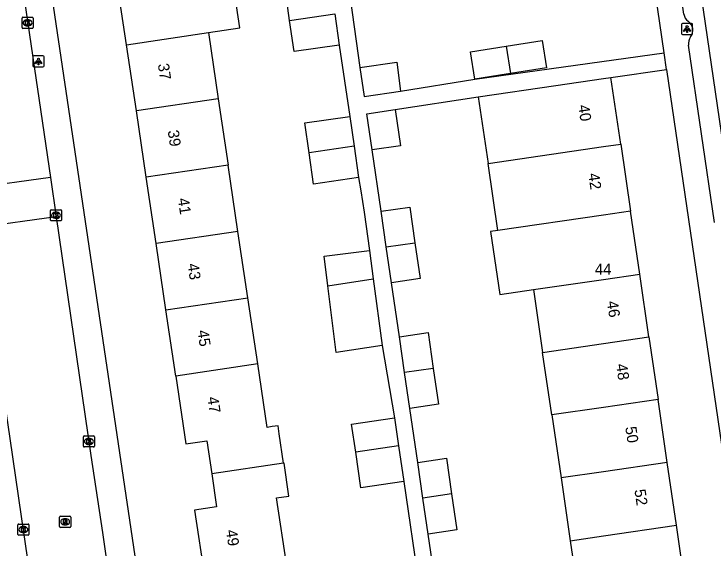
# Model space of a CAD drawing. Extents: x 159053 to 160041, y 380450 to 381422.
# Drawn here: x 159447 to 159509.9, y 381028 to 381076 of the extents above; entities that cross this region are included whole.
import ezdxf

# ---------------------------------------------------------------- set-up
doc = ezdxf.new("R2010")
doc.units = 0
for name, color, linetype in [('IMGEO_Kolk', 7, 'Continuous'), ('IMGEO_Lichtpunt', 7, 'Continuous'), ('IMGEO_Pand', 7, 'Continuous'), ('IMGEO_Pand_nummerreeks', 7, 'Continuous'), ('IMGEO_Rijbaan_lokaal_open', 7, 'Continuous'), ('IMGEO_Rioolput', 7, 'Continuous'), ('IMGEO_Voetpad_open', 7, 'Continuous')]:
    doc.layers.add(name, color=color, linetype=linetype)

msp = doc.modelspace()

# ---------------------------------------------------------------- linework, layer by layer
at = {"layer": 'IMGEO_Kolk'}
for p, q in [((159447.738, 381074.786), (159447.738, 381075.638)), ((159447.813, 381075.712), (159448.665, 381075.712)), ((159448.226, 381075.492), (159448.251, 381075.492)), ((159448.739, 381075.638), (159448.739, 381074.786)), ((159448.249, 381074.932), (159448.224, 381074.932)), ((159448.665, 381074.712), (159447.813, 381074.712)), ((159450.362, 381058.427), (159451.214, 381058.427)), ((159450.287, 381057.501), (159450.287, 381058.353)), ((159450.775, 381058.207), (159450.8, 381058.207)), ((159451.288, 381058.353), (159451.288, 381057.501)), ((159451.214, 381057.427), (159450.362, 381057.427)), ((159450.798, 381057.647), (159450.773, 381057.647)), ((159453.246, 381037.19), (159453.246, 381038.042)), ((159453.321, 381038.116), (159454.173, 381038.116)), ((159453.734, 381037.896), (159453.759, 381037.896)), ((159454.247, 381038.042), (159454.247, 381037.19)), ((159454.173, 381037.116), (159453.321, 381037.116)), ((159453.757, 381037.336), (159453.732, 381037.336)), ((159447.36, 381029.269), (159447.36, 381030.121)), ((159447.435, 381030.195), (159448.287, 381030.195)), ((159448.361, 381030.121), (159448.361, 381029.269)), ((159447.848, 381029.975), (159447.873, 381029.975)), ((159448.287, 381029.195), (159447.435, 381029.195)), ((159447.871, 381029.415), (159447.846, 381029.415))]:
    msp.add_line(p, q, dxfattribs=at)
for points in [[(159447.738, 381074.786), (159447.738, 381075.638)], [(159447.813, 381075.712), (159448.665, 381075.712)], [(159448.059, 381075.412), (159448.182, 381075.412), (159448.182, 381075.261), (159448.312, 381075.412), (159448.476, 381075.412), (159448.33, 381075.261), (159448.483, 381075.012), (159448.331, 381075.012), (159448.246, 381075.176), (159448.182, 381075.109), (159448.182, 381075.012), (159448.059, 381075.012), (159448.059, 381075.412)], [(159448.739, 381075.638), (159448.739, 381074.786)], [(159448.665, 381074.712), (159447.813, 381074.712)], [(159450.362, 381058.427), (159451.214, 381058.427)], [(159450.287, 381057.501), (159450.287, 381058.353)], [(159450.608, 381058.127), (159450.731, 381058.127), (159450.731, 381057.976), (159450.861, 381058.127), (159451.025, 381058.127), (159450.879, 381057.976), (159451.032, 381057.727), (159450.88, 381057.727), (159450.795, 381057.891), (159450.731, 381057.824), (159450.731, 381057.727), (159450.608, 381057.727), (159450.608, 381058.127)], [(159451.288, 381058.353), (159451.288, 381057.501)], [(159451.214, 381057.427), (159450.362, 381057.427)], [(159453.246, 381037.19), (159453.246, 381038.042)], [(159453.321, 381038.116), (159454.173, 381038.116)], [(159453.567, 381037.816), (159453.69, 381037.816), (159453.69, 381037.665), (159453.82, 381037.816), (159453.984, 381037.816), (159453.838, 381037.665), (159453.991, 381037.416), (159453.839, 381037.416), (159453.754, 381037.58), (159453.69, 381037.513), (159453.69, 381037.416), (159453.567, 381037.416), (159453.567, 381037.816)], [(159454.247, 381038.042), (159454.247, 381037.19)], [(159454.173, 381037.116), (159453.321, 381037.116)], [(159447.36, 381029.269), (159447.36, 381030.121)], [(159447.435, 381030.195), (159448.287, 381030.195)], [(159448.361, 381030.121), (159448.361, 381029.269)], [(159447.681, 381029.895), (159447.804, 381029.895), (159447.804, 381029.744), (159447.934, 381029.895), (159448.098, 381029.895), (159447.952, 381029.744), (159448.105, 381029.495), (159447.953, 381029.495), (159447.868, 381029.659), (159447.804, 381029.592), (159447.804, 381029.495), (159447.681, 381029.495), (159447.681, 381029.895)], [(159448.287, 381029.195), (159447.435, 381029.195)]]:
    msp.add_lwpolyline(points, dxfattribs=at)
for centre, start, end in [((159447.815, 381075.636), 91.55205, 178.44795), ((159447.815, 381075.636), 91.55205, 178.44795), ((159448.663, 381075.636), 1.55205, 88.44795), ((159448.663, 381075.636), 1.55205, 88.44795), ((159447.815, 381074.788), 181.55205, 268.44795), ((159447.815, 381074.788), 181.55205, 268.44795), ((159448.663, 381074.788), 271.55205, 358.44795), ((159448.663, 381074.788), 271.55205, 358.44795), ((159450.364, 381058.351), 91.55205, 178.44795), ((159450.364, 381058.351), 91.55205, 178.44795), ((159451.212, 381058.351), 1.55205, 88.44795), ((159451.212, 381058.351), 1.55205, 88.44795), ((159450.364, 381057.503), 181.55205, 268.44795), ((159450.364, 381057.503), 181.55205, 268.44795), ((159451.212, 381057.503), 271.55205, 358.44795), ((159451.212, 381057.503), 271.55205, 358.44795), ((159453.323, 381038.04), 91.55205, 178.44795), ((159453.323, 381038.04), 91.55205, 178.44795), ((159454.171, 381038.04), 1.55205, 88.44795), ((159454.171, 381038.04), 1.55205, 88.44795), ((159453.323, 381037.192), 181.55205, 268.44795), ((159453.323, 381037.192), 181.55205, 268.44795), ((159454.171, 381037.192), 271.55205, 358.44795), ((159454.171, 381037.192), 271.55205, 358.44795), ((159447.437, 381030.119), 91.55205, 178.44795), ((159447.437, 381030.119), 91.55205, 178.44795), ((159448.285, 381030.119), 1.55205, 88.44795), ((159448.285, 381030.119), 1.55205, 88.44795), ((159447.437, 381029.271), 181.55205, 268.44795), ((159447.437, 381029.271), 181.55205, 268.44795), ((159448.285, 381029.271), 271.55205, 358.44795), ((159448.285, 381029.271), 271.55205, 358.44795)]:
    msp.add_arc(centre, 0.0765, start, end, dxfattribs=at)
for centre, major_axis, ratio, start_param, end_param in [((159448.225, 381075.212), (-0.387, 0.002), 0.722429, 4.712389, 7.853982), ((159448.25, 381075.212), (-0.39, 0.002), 0.717154, 1.570796, 4.712389), ((159450.774, 381057.927), (-0.387, 0.002), 0.722429, 4.712389, 7.853982), ((159450.799, 381057.927), (-0.39, 0.002), 0.717154, 1.570796, 4.712389), ((159453.733, 381037.616), (-0.387, 0.002), 0.722429, 4.712389, 7.853982), ((159453.758, 381037.616), (-0.39, 0.002), 0.717154, 1.570796, 4.712389), ((159447.847, 381029.695), (-0.387, 0.002), 0.722429, 4.712389, 7.853982), ((159447.872, 381029.695), (-0.39, 0.002), 0.717154, 1.570796, 4.712389)]:
    msp.add_ellipse(centre, major_axis=major_axis, ratio=ratio, start_param=start_param, end_param=end_param, dxfattribs=at)
at = {"layer": 'IMGEO_Lichtpunt'}
for p, q in [((159507.003, 381075.063), (159507.003, 381074.256)), ((159507.003, 381075.063), (159507.003, 381074.256)), ((159507.905, 381075.158), (159507.097, 381075.158)), ((159507.905, 381075.158), (159507.097, 381075.158)), ((159507.999, 381074.256), (159507.999, 381075.063)), ((159507.999, 381074.256), (159507.999, 381075.063)), ((159507.097, 381074.162), (159507.905, 381074.162)), ((159507.097, 381074.162), (159507.905, 381074.162)), ((159449.617, 381072.252), (159448.809, 381072.252)), ((159449.617, 381072.252), (159448.809, 381072.252)), ((159448.715, 381072.157), (159448.715, 381071.35)), ((159448.715, 381072.157), (159448.715, 381071.35)), ((159449.711, 381071.35), (159449.711, 381072.157)), ((159449.711, 381071.35), (159449.711, 381072.157)), ((159448.809, 381071.256), (159449.617, 381071.256)), ((159448.809, 381071.256), (159449.617, 381071.256))]:
    msp.add_line(p, q, dxfattribs=at)
for points in [[(159507.377, 381074.727), (159507.416, 381074.699), (159507.228, 381074.437), (159507.19, 381074.464), (159507.377, 381074.727)], [(159507.479, 381074.679), (159507.526, 381074.679), (159507.526, 381074.357), (159507.479, 381074.357), (159507.479, 381074.679)], [(159507.589, 381074.699), (159507.627, 381074.726), (159507.814, 381074.464), (159507.775, 381074.436), (159507.589, 381074.699)], [(159449.089, 381071.821), (159449.128, 381071.793), (159448.94, 381071.531), (159448.902, 381071.558), (159449.089, 381071.821)], [(159449.191, 381071.773), (159449.238, 381071.773), (159449.238, 381071.451), (159449.191, 381071.451), (159449.191, 381071.773)], [(159449.301, 381071.793), (159449.339, 381071.82), (159449.526, 381071.558), (159449.487, 381071.53), (159449.301, 381071.793)]]:
    msp.add_lwpolyline(points, dxfattribs=at)
for centre in [(159507.502, 381074.861), (159449.214, 381071.955)]:
    msp.add_circle(centre, 0.0994, dxfattribs=at)
for centre, start, end in [((159507.097, 381075.063), 90, 180), ((159507.097, 381075.063), 90, 180), ((159507.905, 381075.063), 0, 90), ((159507.905, 381075.063), 0, 90), ((159507.097, 381074.256), 180, 270), ((159507.097, 381074.256), 180, 270), ((159507.905, 381074.256), 270, 0), ((159507.905, 381074.256), 270, 360), ((159448.809, 381072.157), 90, 180), ((159448.809, 381072.157), 90, 180), ((159449.617, 381072.157), 0, 90), ((159449.617, 381072.157), 0, 90), ((159448.809, 381071.35), 180, 270), ((159448.809, 381071.35), 180, 270), ((159449.617, 381071.35), 270, 0), ((159449.617, 381071.35), 270, 360)]:
    msp.add_arc(centre, 0.0946, start, end, dxfattribs=at)
at = {"layer": 'IMGEO_Pand'}
for points in [[(159464.484, 381074.347), (159467.305, 381074.767), (159466.419, 381080.722), (159463.598, 381080.302)], [(159457.126, 381073.253), (159456.24, 381079.208)], [(159471.782, 381075.432), (159471.398, 381078.131), (159475.457, 381078.708)], [(159471.782, 381075.432), (159475.838, 381076.035)], [(159475.838, 381076.035), (159476.238, 381073.223)], [(159476.238, 381073.223), (159472.179, 381072.646), (159471.782, 381075.432)], [(159457.126, 381073.253), (159464.484, 381074.347)], [(159464.484, 381074.347), (159465.369, 381068.393)], [(159491.248, 381073.115), (159494.466, 381073.63), (159494.857, 381071.184), (159491.639, 381070.67)], [(159458.011, 381067.299), (159457.126, 381073.253)], [(159488.42, 381070.155), (159488.029, 381072.601), (159491.248, 381073.115)], [(159491.248, 381073.115), (159491.639, 381070.67)], [(159478.097, 381071.199), (159481.405, 381071.68), (159481.758, 381069.077)], [(159478.097, 381071.199), (159478.486, 381068.593), (159481.758, 381069.077)], [(159491.639, 381070.67), (159491.256, 381070.609), (159488.42, 381070.155)], [(159488.733, 381068.555), (159495.714, 381069.578), (159500, 381070.206), (159500.661, 381070.303)], [(159501.537, 381064.318), (159500.661, 381070.303)], [(159488.733, 381068.555), (159489.61, 381062.57)], [(159465.369, 381068.393), (159458.011, 381067.299)], [(159465.369, 381068.393), (159466.255, 381062.438)], [(159458.897, 381061.344), (159458.011, 381067.299)], [(159479.188, 381063.801), (159478.713, 381067.055), (159481.277, 381067.429)], [(159481.277, 381067.429), (159481.752, 381064.175), (159479.188, 381063.801)], [(159473.527, 381063.525), (159473.143, 381066.22), (159477.202, 381066.797)], [(159477.202, 381066.797), (159477.582, 381064.13)], [(159477.582, 381064.13), (159473.527, 381063.525)], [(159477.582, 381064.13), (159477.983, 381061.312)], [(159489.61, 381062.57), (159500, 381064.093), (159501.537, 381064.318)], [(159501.537, 381064.318), (159502.419, 381058.285)], [(159477.983, 381061.312), (159473.924, 381060.735), (159473.527, 381063.525)], [(159466.255, 381062.438), (159458.897, 381061.344)], [(159467.141, 381056.484), (159466.255, 381062.438)], [(159490.491, 381056.556), (159489.61, 381062.57)], [(159459.783, 381055.39), (159458.897, 381061.344)], [(159480, 381058.288), (159482.572, 381058.664), (159483.041, 381055.459)], [(159480.466, 381055.082), (159480, 381058.288)], [(159502.419, 381058.285), (159500, 381057.934), (159490.491, 381056.556)], [(159503.245, 381052.646), (159502.419, 381058.285)], [(159490.491, 381056.556), (159489.839, 381056.462), (159490.667, 381050.814), (159493.694, 381051.255)], [(159467.141, 381056.484), (159459.783, 381055.39)], [(159468.026, 381050.529), (159467.141, 381056.484)], [(159460.668, 381049.435), (159459.783, 381055.39)], [(159480.466, 381055.082), (159483.041, 381055.459)], [(159483.041, 381055.459), (159483.511, 381052.244), (159480.936, 381051.849)], [(159475.221, 381051.599), (159474.89, 381054.251), (159478.962, 381054.76)], [(159478.962, 381054.76), (159479.304, 381052.206)], [(159480.936, 381051.849), (159480.466, 381055.082)], [(159475.221, 381051.599), (159479.304, 381052.206)], [(159479.304, 381052.206), (159480.103, 381046.231)], [(159493.694, 381051.255), (159500, 381052.174), (159503.245, 381052.646)], [(159504.068, 381047.019), (159503.245, 381052.646)], [(159480.103, 381046.231), (159475.969, 381045.614), (159475.221, 381051.599)], [(159493.694, 381051.255), (159494.52, 381045.616)], [(159460.668, 381049.435), (159468.026, 381050.529)], [(159468.912, 381044.575), (159468.026, 381050.529)], [(159461.554, 381043.481), (159460.668, 381049.435)], [(159481.65, 381047.011), (159484.222, 381047.387), (159484.692, 381044.172)], [(159482.121, 381043.795), (159481.65, 381047.011)], [(159494.52, 381045.616), (159500, 381046.421), (159504.068, 381047.019)], [(159504.068, 381047.019), (159504.894, 381041.37)], [(159495.344, 381039.995), (159494.52, 381045.616)], [(159468.912, 381044.575), (159461.554, 381043.481)], [(159471.238, 381035.662), (159470.853, 381038.289), (159470.745, 381039.024), (159470.213, 381038.946), (159469.759, 381038.879), (159468.912, 381044.575)], [(159484.692, 381044.172), (159482.121, 381043.795)], [(159484.692, 381044.172), (159485.163, 381040.957), (159482.591, 381040.581)], [(159461.554, 381043.481), (159462.46, 381037.387), (159464.345, 381037.668), (159464.785, 381034.705)], [(159482.591, 381040.581), (159482.121, 381043.795)], [(159504.894, 381041.37), (159500, 381040.666), (159495.344, 381039.995)], [(159505.719, 381035.733), (159504.894, 381041.37)], [(159477.721, 381036.645), (159477.35, 381039.16), (159481.194, 381039.727)], [(159481.194, 381039.727), (159481.564, 381037.221)], [(159495.344, 381039.995), (159496.173, 381034.336)], [(159481.564, 381037.221), (159477.721, 381036.645)], [(159481.564, 381037.221), (159482.037, 381034.012)], [(159482.037, 381034.012), (159478.193, 381033.445), (159477.721, 381036.645)], [(159483.295, 381035.731), (159485.874, 381036.1), (159486.343, 381032.898)], [(159483.766, 381032.521), (159483.295, 381035.731)], [(159505.719, 381035.733), (159500, 381034.896), (159496.173, 381034.336)], [(159506.546, 381030.085), (159505.719, 381035.733)], [(159471.238, 381035.662), (159464.785, 381034.705)], [(159471.528, 381026.428), (159470.618, 381032.544), (159471.719, 381032.687), (159471.282, 381035.669), (159471.238, 381035.662)], [(159464.785, 381034.705), (159465.226, 381031.742), (159463.24, 381031.447), (159464.149, 381025.331)], [(159496.173, 381034.336), (159496.999, 381028.696)], [(159486.343, 381032.898), (159483.766, 381032.521)], [(159486.343, 381032.898), (159486.815, 381029.671), (159484.239, 381029.297)], [(159484.239, 381029.297), (159483.766, 381032.521)], [(159496.999, 381028.696), (159500, 381029.133), (159506.546, 381030.085)], [(159507.371, 381024.447), (159506.546, 381030.085)], [(159496.999, 381028.696), (159497.826, 381023.057)]]:
    msp.add_lwpolyline(points, dxfattribs=at)
at = {"layer": 'IMGEO_Rijbaan_lokaal_open'}
for points in [[(159444.583, 381100.003), (159450.287, 381061.32)], [(159514.749, 381036.884), (159506.251, 381095.031)], [(159450.287, 381061.32), (159443.344, 381060.378)], [(159450.287, 381061.32), (159450.806, 381057.803)], [(159450.806, 381057.803), (159443.858, 381056.823)], [(159450.806, 381057.803), (159453.929, 381036.365), (159454.981, 381029.422), (159458.014, 381008.022)], [(159451.207, 381006.916), (159447.686, 381030.883), (159446.657, 381037.89), (159443.858, 381056.823)]]:
    msp.add_lwpolyline(points, dxfattribs=at)
at = {"layer": 'IMGEO_Rioolput'}
for p, q in [((159451.11, 381029.972), (159451.11, 381030.824)), ((159451.185, 381030.898), (159452.037, 381030.898)), ((159452.111, 381030.824), (159452.111, 381029.972)), ((159451.621, 381030.118), (159451.596, 381030.118)), ((159451.598, 381030.678), (159451.623, 381030.678)), ((159452.037, 381029.898), (159451.185, 381029.898))]:
    msp.add_line(p, q, dxfattribs=at)
for points in [[(159451.11, 381029.972), (159451.11, 381030.824)], [(159451.185, 381030.898), (159452.037, 381030.898)], [(159452.111, 381030.824), (159452.111, 381029.972)], [(159451.699, 381030.596), (159451.447, 381030.598), (159451.447, 381030.198)], [(159451.447, 381030.198), (159451.571, 381030.198), (159451.571, 381030.36), (159451.582, 381030.36)], [(159451.625, 381030.517), (159451.571, 381030.517), (159451.571, 381030.436)], [(159451.571, 381030.436), (159451.623, 381030.436)], [(159451.629, 381030.331), (159451.7, 381030.198), (159451.84, 381030.198), (159451.775, 381030.324)], [(159452.037, 381029.898), (159451.185, 381029.898)]]:
    msp.add_lwpolyline(points, dxfattribs=at)
for centre, radius, start, end in [((159451.187, 381030.822), 0.0765, 91.55205, 178.44795), ((159451.187, 381030.822), 0.0765, 91.55205, 178.44795), ((159452.035, 381030.822), 0.0765, 1.55205, 88.44795), ((159452.035, 381030.822), 0.0765, 1.55205, 88.44795), ((159451.581, 381030.307), 0.0533, 26.02933, 88.69889), ((159451.607, 381030.625), 0.19, 274.7715, 282.96867), ((159451.631, 381030.421), 0.0964, 77.00612, 93.18647), ((159451.645, 381030.478), 0.0378, 276.66336, 79.67722), ((159451.698, 381030.486), 0.109, 350.36119, 89.41601), ((159451.696, 381030.486), 0.112, 277.58423, 350.98172), ((159451.68, 381030.271), 0.108, 29.51342, 73.79051), ((159451.187, 381029.974), 0.0765, 181.55205, 268.44795), ((159451.187, 381029.974), 0.0765, 181.55205, 268.44795), ((159452.035, 381029.974), 0.0765, 271.55205, 358.44795), ((159452.035, 381029.974), 0.0765, 271.55205, 358.44795)]:
    msp.add_arc(centre, radius, start, end, dxfattribs=at)
for centre, major_axis, ratio, start_param, end_param in [((159451.597, 381030.398), (-0.387, 0.002), 0.722429, 4.712389, 7.853982), ((159451.622, 381030.398), (-0.39, 0.002), 0.717154, 1.570796, 4.712389)]:
    msp.add_ellipse(centre, major_axis=major_axis, ratio=ratio, start_param=start_param, end_param=end_param, dxfattribs=at)
at = {"layer": 'IMGEO_Voetpad_open'}
for points in [[(159474.887, 381094.224), (159478.097, 381071.199)], [(159507.22, 381076.008), (159504.891, 381091.963)], [(159505.448, 381072.514), (159502.714, 381091.198)], [(159448.814, 381088.274), (159461.87, 381000.484)], [(159476.238, 381073.223), (159477.202, 381066.797)], [(159509.96, 381057.273), (159507.631, 381073.206)], [(159488.42, 381070.155), (159505.448, 381072.514)], [(159505.664, 381071.035), (159505.448, 381072.514)], [(159500.661, 381070.303), (159505.664, 381071.035)], [(159505.664, 381071.035), (159512.894, 381021.627), (159515.381, 381005.067)], [(159481.758, 381069.077), (159488.42, 381070.155)], [(159481.277, 381067.429), (159488.733, 381068.555)], [(159480, 381058.288), (159479.188, 381063.801)], [(159477.983, 381061.312), (159478.187, 381060.112), (159478.469, 381058.22), (159478.962, 381054.76)], [(159481.65, 381047.011), (159480.936, 381051.849)], [(159480.103, 381046.231), (159481.194, 381039.727)], [(159483.295, 381035.731), (159482.591, 381040.581)], [(159482.037, 381034.012), (159483.391, 381024.787)], [(159484.955, 381024.427), (159484.239, 381029.297)]]:
    msp.add_lwpolyline(points, dxfattribs=at)
for centre, radius, start, end in [((159508.121, 381076.092), 0.905, 185.29688, 234.92276), ((159507.044, 381074.548), 0.977, 322.25694, 55.27226), ((159508.56, 381073.369), 0.943, 141.96735, 189.96016)]:
    msp.add_arc(centre, radius, start, end, dxfattribs=at)

# ---------------------------------------------------------------- texts
at = {"layer": 'IMGEO_Pand_nummerreeks'}
for s, rotation, p in [('37', 278.45904, (159459.935, 381071.498)), ('40', 278.32428, (159497.713, 381067.787)), ('39', 278.45904, (159460.825, 381065.512)), ('42', 278.32156, (159498.613, 381061.648)), ('41', 278.45904, (159461.733, 381059.414)), ('43', 278.45904, (159462.606, 381053.54)), ('46', 278.32428, (159500.291, 381050.171)), ('45', 278.45904, (159463.496, 381047.554)), ('48', 278.32428, (159501.116, 381044.53)), ('47', 278.45665, (159464.386, 381041.569)), ('50', 278.32428, (159501.941, 381038.892)), ('52', 278.32428, (159502.766, 381033.26)), ('49', 278.45665, (159466.059, 381029.626))]:
    msp.add_text(s, height=1, rotation=rotation, dxfattribs=at).set_placement(p)
msp.add_text('44', height=1, dxfattribs=at).set_placement((159499.21, 381052.584))

doc.saveas('drawing.dxf')
